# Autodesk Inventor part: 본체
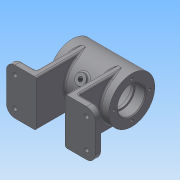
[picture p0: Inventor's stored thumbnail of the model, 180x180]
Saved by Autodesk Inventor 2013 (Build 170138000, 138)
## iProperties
Created: 2017-02
Part Number: 본체
Material: 일반
Document SubType Name: Modeling
Designer: Administrator
Density: 1 g/cm^3
Author: Administrator
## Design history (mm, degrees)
sketch "스케치1"
  geometry: L1 (-35, 27)-(35, 27); L2 (35, 27)-(35, 16); L3 (35, 0)-(-35, 0); L4 (-35, 16)-(-23, 16); L5 (-23, 16)-(-23, 14); L6 (-23, 14)-(-20, 14); L7 (-20, 14)-(-20, 22); L8 (-20, 22)-(20, 22); L9 (20, 22)-(20, 14); L10 (20, 14)-(23, 14); L11 (23, 14)-(23, 16); L12 (23, 16)-(35, 16); L13 (-35, 16)-(-35, 27); 2 further points
  constraints: 26 end point, 9 parallel, 2 perpendicular, 1 coincident, 1 collinear, 1 midpoint, 1 vertical
  dimensions: "d0" = 70 distance of L1.start L1.end; "d2" = 27 distance of L1.end L3.start; "d3" = 40 distance of L7.end L8.end; "d4" = 12 distance of L4.start L4.end; "d5" = 12 distance of L11.end L2.end; "d6" = 3 distance of L5.end L6.end; "d7" = 44 diameter of L8 L3; "d8" = 32 diameter of L12 L3; "d9" = 32 diameter of L4 L3; "d10" = 28 diameter of L6 L3; "d11" = 28 diameter of L10 L3; "d12" = 70 distance of L3.start L3.end; "d13" = 16 distance of L3.start L2.end
revolve "회전1" sketch "스케치1" stored, may be unused: angle "d14" = 90 deg
fillet "모깎기1" dims "d15" = 0.3
chamfer "모따기1" distance "d16" = 1; stored, may be unused: second distance "d17" = 2, angle "d18" = 45 deg
node "작업 평면1"
sketch "스케치2"
  geometry: L1 (-52, 27)-(-52, -27); L2 (-52, -27)-(-17, -27); L3 (-17, -27)-(-17, 27); L4 (-17, 27)-(-52, 27); L5 (17, 27)-(17, -27); L6 (17, -27)-(52, -27); L7 (52, -27)-(52, 27); L8 (52, 27)-(17, 27); 1 further point
  constraints: 16 end point, 4 vertical, 2 horizontal, 2 perpendicular, 1 collinear
  dimensions: "d21" = 54 distance of L1.start L1.end; "d23" = 54 distance of L5.start L5.end; "d24" = 35 distance of L3.end L1.start; "d25" = 35 distance of L7.end L5.start; "d26" = 17 distance from line of point (0, 0) L3; "d27" = 17 distance from line of L5 point (0, 0); "d28" = 27 distance from line of point (0, 0) L2
extrude "돌출1" join sketch "스케치2" distance "d29" = 8; taper "d30" = 0 deg
fillet "모깎기2" dims "d31" = 10
sketch "스케치3"
  geometry: L1 (-42, -27)-(-17, -27) reference; L2 (-17, -27)-(-17, 27) reference; L3 (-17, 27)-(-42, 27) reference; L4 (-25, 27)-(-25, -27); L5 (25, 27)-(25, -27); L6 (17, 27)-(17, -27) reference; L7 (-17, -27)-(-17, 27) reference; L8 (-17, 27)-(-42, 27) reference; L9 (-42, -27)-(-17, -27) reference; L10 (17, -27)-(42, -27) reference; L11 (42, 27)-(17, 27) reference; L12 (-25, 27)-(-17, 27); L13 (-17, -27)-(-25, -27); L14 (25, -27)-(17, -27); L15 (17, 27)-(25, 27); 1 further point
  constraints: 12 end point, 3 collinear, 2 parallel, 2 point on line, 1 perpendicular
  dimensions: "d32" = 8 distance between parallel lines of L2 L4; "d33" = 8 distance between parallel lines of L6 L5
extrude "돌출2" join sketch "스케치3" stored distance "d34" = 8; taper "d35" = 0 deg
sketch "스케치4"
  geometry: L1 (-25, 27)-(-42, 27) reference; L2 (-52, 17)-(-52, -17) reference; 3 further points
  dimensions: "d36" = 34 distance of point (-42, -17) point (-42, 17); "d38" = 10 distance from line of L1 point (-42, 17); "d39" = 10 distance from line of L2 point (-42, 17); "d40" = 10 distance from line of L2 point (-42, -17)
hole "구멍1" sketch "스케치4" at (-42, -17), (-42, 17) diameter "d41" = 5; stored, may be unused: countersink angle "d45" = 90 deg, drill point angle "d47" = 118 deg; dims "d42" = 6, "d43" = 3, "d44" = 2, "d46" = 8
fillet "모깎기3" dims "d59" = 2
sketch "스케치6"
  geometry: C1 r 27 at (0, 0) reference; 4 further points
  constraints: 2 horizontal alignment, 2 vertical alignment
  dimensions: "d60" = 21 distance of C1.centre point (0, 21); "d61" = 21 distance of point (0, -21) C1.centre; "d62" = 21 distance of point (21, 0) C1.centre; "d63" = 21 distance of point (-21, 0) C1.centre
hole "구멍2" sketch "스케치6" at (0, 21), (-21, 0), (0, -21), (21, 0) diameter "d64" = 3.242; stored, may be unused: countersink angle "d68" = 90 deg, drill point angle "d70" = 118 deg; dims "d65" = 8, "d66" = 4, "d67" = 2, "d69" = 10
node "작업 평면2"
sketch "스케치7"
  geometry: L1 (-35, 27)-(-35, -27) reference; C1 r 5 at (-10, 0); 1 further point
  constraints: 1 centre point, 1 horizontal alignment
  dimensions: "d71" = 10 diameter of C1; "d72" = 25 distance from line of C1.centre L1
extrude "돌출4" join sketch "스케치7" distance "d73" = 5; taper "d75" = 0 deg; dims "d74" = 3, "d76" = 0
fillet "모깎기4" dims "d77" = 2
sketch "스케치8"
  geometry: C1 r 5 at (0, 0) reference; 2 further points
  constraints: 1 coincident
hole "구멍3" sketch "스케치8" at (0, 0) diameter "d78" = 5.188; stored, may be unused: countersink angle "d82" = 90 deg, drill point angle "d84" = 118 deg; dims "d79" = 6, "d80" = 4, "d81" = 2, "d83" = 10
sketch "스케치9"
  geometry: L1 (0, 0)-(-25.16, 16.339); L2 (0, 0)-(-26.936, 0)
  constraints: 4 end point, 1 horizontal
  dimensions: "d85" = 33 deg angle of L2 L1; "d86" = 30 distance of L1.start L1.end; "d87" = 26.93621 distance of L1.start L2.end
node "작업 평면3"
sketch "스케치10"
  geometry: L1 (30, 0)-(30, 6); L2 (30, 6)-(24, 6); L3 (24, 6)-(24, 0); L4 (24, 0)-(30, 0); 1 further point
  constraints: 8 end point, 1 parallel, 1 perpendicular, 1 vertical
  dimensions: "d89" = 6 distance of L1.start L1.end; "d90" = 6 distance of L1.end L2.end; "d91" = 6 distance of L2.end L3.end; "d92" = 6 distance of L3.end L1.start (derived)
revolve "회전2" sketch "스케치10" stored, may be unused: angle "d93" = 90 deg
sketch "스케치11"
  geometry: C1 r 6 at (0, 0) reference; 1 further point
  constraints: 1 coincident
hole "구멍4" sketch "스케치11" at (0, 0) diameter "d94" = 5.188; stored, may be unused: countersink angle "d98" = 90 deg, drill point angle "d100" = 118 deg; dims "d95" = 6, "d96" = 4, "d97" = 2, "d99" = 10
fillet "모깎기5" dims "d101" = 3
fillet "모깎기6" dims "d102" = 2
node "작업 평면4"
sketch "스케치12"
  geometry: L1 (35, 27)-(-35, 27) reference; L2 (-35, 27)-(-35, -27) reference; 2 further points
  constraints: 1 other
  dimensions: "d103" = 0 distance of point (0, 0) point (0, 0); "d104" = 35 distance from line of L2 point (0, 0)
feature "엠보싱1" sketch "스케치12" dims "d0" = 70, "d2" = 27, "d3" = 40, "d4" = 12, "d5" = 12, "d6" = 3, "d7" = 44, "d8" = 32, "d9" = 32, "d10" = 28, "d11" = 28, "d12" = 70, "d13" = 16, "d16" = 1, "d105" = 0.5, "d106" = 0
sketch "스케치13"
  geometry: L1 (-39.113, 22)-(-36.226, 17); L2 (-36.226, 17)-(-39.113, 12); L3 (-39.113, 12)-(-44.887, 12); L4 (-44.887, 12)-(-47.774, 17); L5 (-47.774, 17)-(-44.887, 22); L6 (-44.887, 22)-(-39.113, 22); C1 r 2.5 at (-42, 17) reference; 2 further points
  constraints: 12 end point, 1 coincident, 1 horizontal, 13 other
  dimensions: "d109" = 5 distance from line of point (-42, 17) L6
extrude "돌출5" cut sketch "스케치13" distance "d110" = 3; taper "d111" = 0 deg
node "솔리드1"
mirror "대칭1"
mirror "대칭2"
pattern_linear "직사각형 패턴2" dims "d114" = 34, "d117" = 84
other parameters: "d88" = 90 deg
